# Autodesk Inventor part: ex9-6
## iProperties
Created: 2006-03
Part Number: ex9-6
Document SubType Name: Sheet Metal
Designer: Elise Moss
Author: Elise Moss
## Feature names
1. Plate1
2. Bend1
3. Plate2
4. Bend2
5. Cut1
